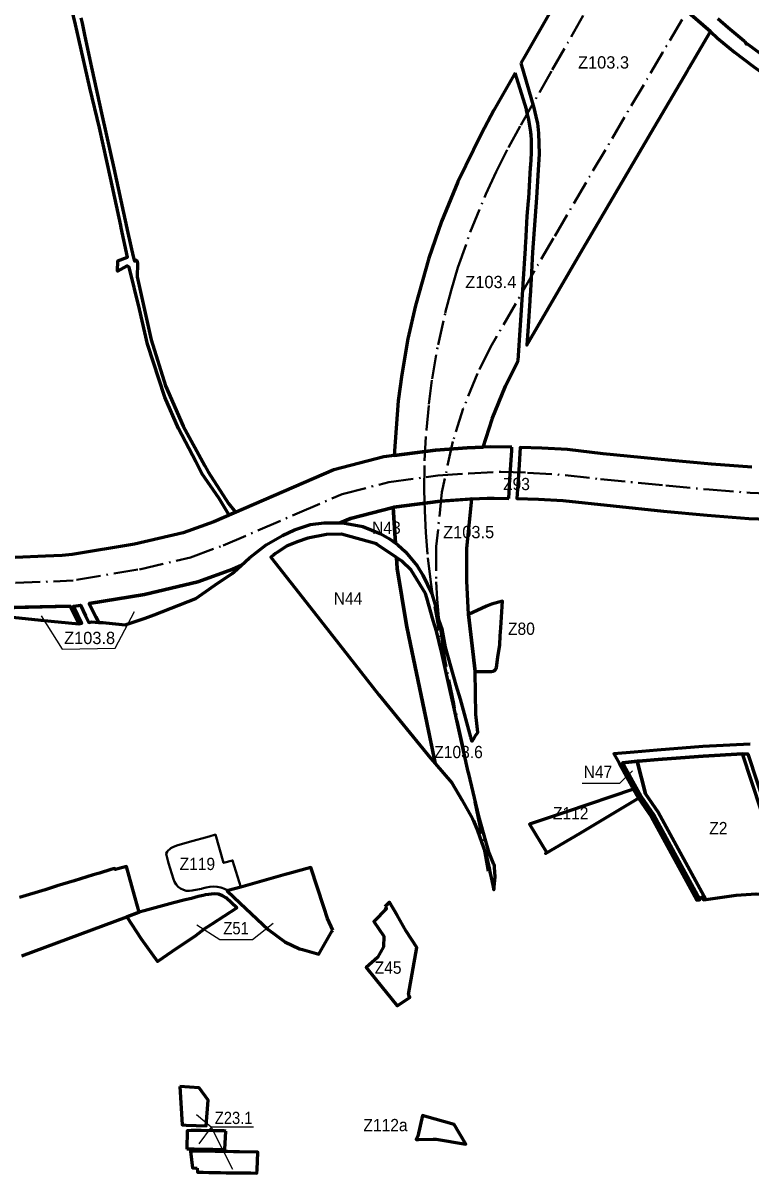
# Model space of a CAD drawing. Extents: x -650277 to -643425, y -1073980 to -1066720.
# Drawn here: x -648765 to -647342, y -1070372 to -1068122 of the extents above; entities that cross this region are included whole.
import ezdxf

# ---------------------------------------------------------------- set-up
doc = ezdxf.new("R2010")
doc.units = 0
doc.header["$LTSCALE"] = 9.6
doc.linetypes.add('DOT_DASHED', pattern=[7.7, 5, -1.2, 0.3, -1.2])
for name, color, linetype, lineweight in [('1', 7, 'Continuous', 60), ('15', 7, 'Continuous', 60), ('3', 7, 'Continuous', 60), ('35', 7, 'Continuous', 60), ('36', 7, 'Continuous', 60), ('42', 7, 'Continuous', 60), ('60', 7, 'Continuous', 60), ('61', 7, 'Continuous', 60), ('62', 7, 'DOT_DASHED', 40), ('63', 7, 'Continuous', 25), ('9', 7, 'Continuous', 60)]:
    doc.layers.add(name, color=color, linetype=linetype, lineweight=lineweight)

msp = doc.modelspace()

# ---------------------------------------------------------------- linework, layer by layer
at = {"layer": '1'}
for points in [[(-647356.899, -1069552.034), (-647433.779, -1069556.106), (-647433.779, -1069556.106), (-647513.66, -1069562.249), (-647514.067, -1069562.282), (-647560.836, -1069566.036), (-647563.104, -1069566.28)], [(-647563.104, -1069566.28), (-647546.777, -1069629.901), (-647521.943, -1069665.763)], [(-647369.3, -1069828.22), (-647330.46, -1069825.51), (-647294.38, -1069826.88), (-647270.09, -1069827.02), (-647266.581, -1069827.042), (-647356.899, -1069552.034)], [(-647521.943, -1069665.763), (-647428.993, -1069836.714), (-647369.3, -1069828.22)], [(-648368.25, -1070289.71), (-648372.1, -1070289.59), (-648380.97, -1070289.44), (-648392.94, -1070289.25), (-648416.93, -1070288.85), (-648420.39, -1070288.79), (-648428.98, -1070288.92), (-648435.93, -1070288.95), (-648444.15, -1070289.16), (-648444.85, -1070324.47)], [(-648444.85, -1070324.47), (-648444.85, -1070324.47), (-648430.02, -1070324.76), (-648418.1, -1070325), (-648406.09, -1070325.23), (-648394.08, -1070325.47), (-648382.06, -1070325.7), (-648370.07, -1070325.94), (-648368.25, -1070289.71)], [(-648307.13, -1070365.57), (-648305.47, -1070331.23), (-648341.46, -1070330.48), (-648353.32, -1070330.23), (-648365.35, -1070329.98), (-648389.43, -1070329.58), (-648401.41, -1070329.39), (-648413.45, -1070329.19), (-648425.43, -1070329), (-648437.65, -1070328.8), (-648433.46, -1070361.94), (-648424.31, -1070362.21)], [(-648424.31, -1070362.21), (-648424.05, -1070370), (-648412.75, -1070370.28), (-648401.35, -1070370.5), (-648390.06, -1070370.72), (-648378.73, -1070370.94), (-648367.67, -1070371.16), (-648355.67, -1070371.28), (-648343.67, -1070371.41), (-648331.67, -1070371.53), (-648319.67, -1070371.65), (-648307.67, -1070371.78), (-648307.13, -1070365.57)]]:
    msp.add_lwpolyline(points, dxfattribs=at)
at = {"layer": '1', "lineweight": 40}
msp.add_lwpolyline([(-648339.05, -1069812.45), (-648363.68, -1069819.31), (-648371.21, -1069815.56), (-648378.1, -1069813.29), (-648385.21, -1069811.91), (-648392.45, -1069811.44), (-648399.68, -1069811.88), (-648406.84, -1069813.23), (-648414.657, -1069815.246), (-648415.99, -1069815.59), (-648430.881, -1069818.663), (-648433.97, -1069819.3), (-648439.89, -1069819.97), (-648445.8, -1069819.51), (-648451.53, -1069817.98), (-648456.88, -1069815.39), (-648461.64, -1069811.86), (-648465.67, -1069807.49), (-648468.82, -1069802.44), (-648470.97, -1069796.9), (-648480.267, -1069765.316), (-648485.44, -1069747.39), (-648485.14, -1069746.55), (-648483.274, -1069743.777), (-648481.79, -1069741.57), (-648477.39, -1069737.44), (-648476.022, -1069736.525), (-648472.4, -1069734.1), (-648464.45, -1069730.89), (-648439.8, -1069724.19), (-648401.288, -1069713.154), (-648388.631, -1069709.738), (-648372.639, -1069765.241), (-648355.015, -1069760.287)], close=True, dxfattribs=at)
at = {"layer": '1'}
msp.add_lwpolyline([(-648458.28, -1070202.26), (-648454.038, -1070277.767), (-648446.18, -1070278.15), (-648406.8, -1070279.32), (-648403.04, -1070229.15), (-648420.7, -1070204.96)], close=True, dxfattribs=at)
at = {"layer": '15'}
for points in [[(-648349.419, -1069079.223), (-648362.06, -1069084.664), (-648381.44, -1069052.48), (-648415.29, -1069003.16), (-648419.78, -1068994.25), (-648427.21, -1068980.13), (-648461.22, -1068915.44), (-648488.09, -1068854.16), (-648521.92, -1068750.34), (-648537.29, -1068681.95), (-648557.4, -1068599.9), (-648559.44, -1068598.37), (-648561.49, -1068596.84), (-648580.66, -1068607.64), (-648579.97, -1068587.39), (-648560.79, -1068580.12), (-648572.95, -1068522.97), (-648573.96, -1068518.34), (-648594.38, -1068425.02), (-648615.87, -1068327.3), (-648634.84, -1068248.76), (-648655.88, -1068153.63), (-648662.71, -1068124.76), (-648677.61, -1068061.74)], [(-648651.89, -1068111.95), (-648649.74, -1068121.95), (-648644.73, -1068145.27), (-648630.99, -1068209.19), (-648610.14, -1068304.32), (-648587.39, -1068405.82), (-648559.91, -1068532.62), (-648549.84, -1068578.65), (-648547.25, -1068588.14), (-648542.93, -1068586.13), (-648541.74, -1068589.27)], [(-648541.74, -1068589.27), (-648541.25, -1068592.3), (-648541.89, -1068618.64), (-648514.35, -1068741.53), (-648486.25, -1068831.83), (-648451.76, -1068910.91), (-648409.15, -1068988.44), (-648402.76, -1069000.2), (-648363.11, -1069061.72), (-648349.419, -1069079.223)], [(-647341.697, -1069532.602), (-647434.969, -1069537.141), (-647523.931, -1069544.499), (-647568.792, -1069548.21), (-647608.81, -1069551.868), (-647598.735, -1069570.026), (-647573.15, -1069616.16), (-647570.37, -1069621.18), (-647560.36, -1069638.39), (-647535.588, -1069674.163), (-647446.322, -1069838.338), (-647441.19, -1069837.6), (-647440.46, -1069836.558), (-647530.471, -1069671.013), (-647555.266, -1069635.207), (-647592.199, -1069569.411), (-647560.836, -1069566.036), (-647514.067, -1069562.282), (-647513.66, -1069562.249), (-647433.779, -1069556.106), (-647433.779, -1069556.106), (-647356.899, -1069552.034), (-647346.554, -1069551.486), (-647256.034, -1069827.107)]]:
    msp.add_lwpolyline(points, dxfattribs=at)
at = {"layer": '3'}
msp.add_lwpolyline([(-648767.83, -1069946.87), (-648562.242, -1069870.301), (-648537.86, -1069861.22), (-648541.06, -1069849.78), (-648546.97, -1069828.68), (-648562.87, -1069771.85), (-648579.63, -1069776.66), (-648584.65, -1069778.1), (-648586.09, -1069775.75), (-648593.59, -1069778.06), (-648615.88, -1069784.93), (-648627.99, -1069788.67), (-648665.05, -1069799.99), (-648698.31, -1069810.16), (-648722.24, -1069817.54), (-648772.48, -1069832.83)], dxfattribs=at)
for points in [[(-648159.1, -1069896.39), (-648169.15, -1069873.81), (-648176.78, -1069851.74), (-648201.83, -1069773.86), (-648247.27, -1069786.64), (-648251.94, -1069787.95), (-648339.05, -1069812.45), (-648363.68, -1069819.31), (-648365.81, -1069819.9), (-648340.38, -1069843.78), (-648285.62, -1069895.71), (-648253.13, -1069919.7), (-648223.99, -1069932.96), (-648218.245, -1069934.595), (-648186.268, -1069943.697), (-648160.04, -1069897.73)], [(-648470.79, -1069843.51), (-648528.11, -1069858.73), (-648537.86, -1069861.22), (-648562.242, -1069870.301), (-648533.79, -1069913.49), (-648502.048, -1069957.969), (-648472.6, -1069937.81), (-648426.82, -1069906.88), (-648409.44, -1069893.25), (-648396.87, -1069885.43), (-648395.03, -1069884.22), (-648347.06, -1069853), (-648367.64, -1069833.35), (-648374.89, -1069829.22), (-648382.8, -1069826.55), (-648391.08, -1069825.45), (-648408.45, -1069827.83), (-648412.74, -1069828.72), (-648422.75, -1069830.78), (-648435.53, -1069834.44), (-648447.98, -1069837.44)], [(-648057.11, -1069851.12), (-648053.61, -1069854.64), (-648078.54, -1069880.01), (-648059.32, -1069908.27), (-648059.5, -1069929.52), (-648071.58, -1069950.39), (-648093.67, -1069969.42), (-648074.96, -1069993.46), (-648032.85, -1070044.73), (-648008.18, -1070028.25), (-648010.44, -1070023.66), (-648010.94, -1070022.65), (-647994.71, -1069930.53), (-648015.11, -1069898.98), (-648032.94, -1069867.46), (-648048.08, -1069841.95)]]:
    msp.add_lwpolyline(points, close=True, dxfattribs=at)
at = {"layer": '35'}
msp.add_lwpolyline([(-647740.74, -1069744.24), (-647742.36, -1069746.93), (-647674.901, -1069706.701), (-647560.36, -1069638.39), (-647570.37, -1069621.18), (-647701.61, -1069665.279), (-647774.11, -1069689.64)], close=True, dxfattribs=at)
at = {"layer": '36'}
msp.add_lwpolyline([(-647962.82, -1070305.9), (-647956.36, -1070305.77), (-647898.82, -1070315.51), (-647921.51, -1070276.76), (-647979.24, -1070260.71), (-647983.6, -1070259.5), (-647992.71, -1070300.01), (-647995.46, -1070306.55), (-647991.12, -1070306.46)], close=True, dxfattribs=at)
at = {"layer": '42'}
for points in [[(-648100.37, -1069107.1), (-648065.16, -1069121.12), (-648048.06, -1069130.81), (-648036.291, -1069139.458), (-648040.705, -1069069.547), (-648124.327, -1069091.181), (-648144.867, -1069099.987), (-648139.27, -1069100.05), (-648100.37, -1069107.1)], [(-647555.266, -1069635.207), (-647530.471, -1069671.013), (-647440.46, -1069836.558), (-647437.46, -1069832.27), (-647433.32, -1069837.33), (-647428.993, -1069836.714), (-647521.943, -1069665.763), (-647546.777, -1069629.901), (-647563.104, -1069566.28), (-647592.199, -1069569.411)]]:
    msp.add_lwpolyline(points, close=True, dxfattribs=at)
at = {"layer": '60'}
for points in [[(-647618.773, -1067899.914), (-647553.628, -1067999.427), (-647472.338, -1068093.096), (-647419.713, -1068138.871)], [(-647295.47, -1068201.09), (-647347.74, -1068162.54), (-647349.59, -1068163.24), (-647350.6, -1068160.26), (-647353.81, -1068157.67), (-647385.13, -1068131.51), (-647405.026, -1068113.904)], [(-647419.713, -1068138.871), (-647405.71, -1068151.74), (-647372.38, -1068179.01), (-647337.74, -1068205.67), (-647334.62, -1068208.02), (-647307.39, -1068227.44), (-647281.64, -1068244.34), (-647234.11, -1068273.04), (-647230.83, -1068274.93), (-647174.56, -1068306.35), (-647142.788, -1068322.462), (-647130.29, -1068328.8), (-647079.16, -1068357.01), (-647032.91, -1068382.51), (-647029.23, -1068384.46), (-646997.06, -1068401.37), (-646929.56, -1068435.42), (-646927.06, -1068436.66)], [(-647864.531, -1068951.823), (-647895.901, -1068953.392), (-647958.168, -1068957.73), (-648038.596, -1068968.281), (-648038.759, -1068968.54)], [(-647808.28, -1068952.066), (-647850.043, -1068951.098), (-647864.531, -1068951.823)], [(-647814.401, -1069052.246), (-647812.34, -1069014.54), (-647808.67, -1068958.06), (-647808.28, -1068952.066)], [(-647338.816, -1068991.19), (-647417.895, -1068984.986), (-647502.412, -1068977.157), (-647629.424, -1068964.608), (-647699.561, -1068956.635), (-647749.978, -1068953.416), (-647792.01, -1068952.442), (-647794.21, -1068986.12), (-647796.13, -1069015.57), (-647798.631, -1069052.508), (-647756.441, -1069053.207), (-647708.401, -1069056.275), (-647511.94, -1069076.703), (-647426.417, -1069084.624), (-647344.902, -1069091.02), (-647270.522, -1069094.255)], [(-648038.759, -1068968.54), (-648038.746, -1068968.301), (-648058.764, -1068970.927), (-648156.739, -1068996.273), (-648392.002, -1069097.554), (-648451.865, -1069119.456), (-648547.243, -1069141.81), (-648668.959, -1069161.838), (-648688.912, -1069163.603), (-648721.315, -1069164.952), (-648781.015, -1069167.44)], [(-648040.705, -1069069.547), (-648039.666, -1069069.279), (-647948.18, -1069057.276), (-647886.615, -1069053.052), (-647856.541, -1069051.548), (-647848.615, -1069051.679), (-647842.888, -1069051.774), (-647814.401, -1069052.246)], [(-648918.889, -1069268.875), (-648673.267, -1069262.895), (-648656.242, -1069297.116), (-648650.06, -1069296.39), (-648650.58, -1069295.34), (-648658.18, -1069280.27), (-648666.827, -1069262.738), (-648665.007, -1069262.694), (-648665.007, -1069262.694), (-648652.716, -1069260.657), (-648642.74, -1069281.93), (-648636.85, -1069294.49), (-648630.82, -1069293.63), (-648617.434, -1069294.508), (-648635.818, -1069257.857), (-648527.693, -1069239.938), (-648423.173, -1069215.44), (-648354.978, -1069190.492), (-648338.523, -1069183.389), (-648322.14, -1069168.56), (-648306.83, -1069156.57), (-648289.25, -1069142.79), (-648257.5, -1069124.41), (-648234.22, -1069113.6), (-648202.46, -1069103.3), (-648175.65, -1069099.64), (-648144.866, -1069099.987), (-648124.327, -1069091.181), (-648040.705, -1069069.547)], [(-648526.15, -1069286.21), (-648508.95, -1069280.01), (-648427.08, -1069247.75), (-648407.73, -1069233.88), (-648389.91, -1069221.86), (-648355.81, -1069198.88), (-648351.77, -1069195.88), (-648338.523, -1069183.389), (-648354.978, -1069190.492)], [(-648354.978, -1069190.492), (-648423.173, -1069215.44), (-648527.693, -1069239.938), (-648635.818, -1069257.857)], [(-648635.818, -1069257.857), (-648622.995, -1069283.455), (-648617.434, -1069294.508)], [(-648617.434, -1069294.508), (-648609.425, -1069295.033), (-648603.228, -1069295.53), (-648565.18, -1069299.46), (-648526.15, -1069286.21)]]:
    msp.add_lwpolyline(points, dxfattribs=at)
for points in [[(-647860.52, -1069390.72), (-647848.24, -1069390.65), (-647845.25, -1069390.07), (-647843.41, -1069389.23), (-647841.81, -1069387.99), (-647840.42, -1069386.51), (-647839.4, -1069384.73), (-647838.79, -1069382.86), (-647836.2, -1069362.68), (-647832.29, -1069338.58), (-647832.29, -1069338.58), (-647831.19, -1069320.69), (-647830.23, -1069305.38), (-647826.928, -1069253.199), (-647848.17, -1069259.21), (-647858.37, -1069263.03), (-647893.553, -1069279.017), (-647880.326, -1069390.832)], [(-648730.66, -1069290.43), (-648656.242, -1069297.116), (-648673.267, -1069262.895), (-648761.189, -1069265.035), (-648918.889, -1069268.875), (-648909.86, -1069270.02), (-648861.49, -1069275.34), (-648785.92, -1069284.2), (-648730.66, -1069290.43)]]:
    msp.add_lwpolyline(points, close=True, dxfattribs=at)
msp.add_arc((-648354.978, -1069190.492), 0.000000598, 264.13978, 298.69712, dxfattribs=at)
at = {"layer": '61'}
msp.add_line((-648038.596, -1068968.281), (-647958.168, -1068957.73), dxfattribs=at)
for points in [[(-647464.94, -1068215.752), (-647461.188, -1068209.373), (-647419.713, -1068138.871), (-647472.338, -1068093.096), (-647553.628, -1067999.427), (-647618.773, -1067899.914), (-647685.819, -1068016.861)], [(-647685.819, -1068016.861), (-647781.346, -1068183.485), (-647791.055, -1068200.507)], [(-647801.797, -1068219.34), (-647843.6, -1068292.629), (-647868.214, -1068337.803), (-647914.339, -1068432.512), (-647946.187, -1068510.254), (-647971.074, -1068581.98), (-647997.27, -1068674.747), (-648011.775, -1068739.718), (-648023.914, -1068809.332), (-648030.73, -1068861.213), (-648038.596, -1068968.281)], [(-647771.413, -1068334.626), (-647774.94, -1068311.47), (-647779.55, -1068292.23), (-647780.07, -1068290.53), (-647801.797, -1068219.34)], [(-647791.055, -1068200.507), (-647765.22, -1068287.94), (-647759.412, -1068313.436)], [(-647768.02, -1068570.36), (-647770.94, -1068622.47), (-647772.85, -1068656.41), (-647773.08, -1068660.57), (-647773.4, -1068665.71), (-647776.5, -1068714.8), (-647778.95, -1068752.433), (-647675.054, -1068572.919), (-647535.844, -1068336.279), (-647464.94, -1068215.752)], [(-647759.412, -1068313.436), (-647758.45, -1068317.66), (-647756.09, -1068337.61), (-647754.99, -1068378.21), (-647757.41, -1068419.98), (-647760.22, -1068463.96), (-647768.02, -1068570.36)], [(-647796.173, -1068782.191), (-647791.77, -1068713.23), (-647786.47, -1068634.37), (-647786.32, -1068632.19), (-647781.85, -1068562.97), (-647781.55, -1068558.38), (-647781.13, -1068551.88), (-647778.24, -1068499.95), (-647775.82, -1068469.74), (-647775.52, -1068464.97), (-647771.74, -1068404.5), (-647771.47, -1068400.07), (-647770.12, -1068377.5), (-647769.92, -1068352.1), (-647770.81, -1068340.29), (-647771.05, -1068337.01), (-647771.413, -1068334.626)], [(-647846.989, -1068896.545), (-647820.883, -1068832.117), (-647797.632, -1068784.713), (-647796.173, -1068782.191)], [(-647958.168, -1068957.73), (-647895.901, -1068953.392), (-647864.531, -1068951.823), (-647847.197, -1068897.199), (-647847.034, -1068896.687), (-647846.989, -1068896.545)], [(-647886.615, -1069053.052), (-647889.927, -1069053.218), (-647948.18, -1069057.276)], [(-647893.553, -1069279.017), (-647896.67, -1069213.573), (-647896.362, -1069149.171), (-647886.615, -1069053.052)], [(-647948.18, -1069057.276), (-648039.666, -1069069.279), (-648040.705, -1069069.548), (-648036.291, -1069139.458)], [(-648036.291, -1069139.458), (-648031.92, -1069142.67), (-648016.36, -1069156.54), (-647993.8, -1069184.11)], [(-648005.47, -1069192.09), (-648024.02, -1069174.7), (-648034.421, -1069167.61)], [(-648034.421, -1069167.61), (-648034.421, -1069167.61), (-648033, -1069189), (-648015, -1069300), (-648010.092, -1069322.087), (-647980.331, -1069465.915), (-647958.34, -1069570.699), (-647925.99, -1069608.57), (-647906.16, -1069641.48), (-647885.665, -1069678.788), (-647885.663, -1069678.794), (-647883.51, -1069682.71), (-647875.82, -1069701.85), (-647875.82, -1069701.85), (-647864.19, -1069735.12), (-647858.44, -1069749.43), (-647852.63, -1069775.7), (-647850.66, -1069785.74), (-647849.165, -1069793.367)], [(-647993.8, -1069184.11), (-647982.58, -1069202.33), (-647965.06, -1069238.95), (-647957.56, -1069264.74), (-647953.01, -1069285.73), (-647951.841, -1069289.09)], [(-647962.2, -1069290.88), (-647974.81, -1069246.86), (-647977.29, -1069238.21), (-648005.47, -1069192.09)], [(-647852.78, -1069745.71), (-647859.722, -1069722.428), (-647872.87, -1069673.56), (-647892.79, -1069591.06), (-647892.789, -1069591.06), (-647893.75, -1069587.08), (-647922.04, -1069459.71), (-647925.16, -1069445.68), (-647928.41, -1069431.03), (-647945.28, -1069355.1), (-647956.27, -1069311.58), (-647962.2, -1069290.88)], [(-647951.841, -1069289.09), (-647945.63, -1069306.95), (-647938.77, -1069343.17), (-647918.08, -1069417.43), (-647909.67, -1069444.46), (-647889.22, -1069519.32), (-647887.087, -1069527.229), (-647885.782, -1069525.389), (-647882.551, -1069520.835), (-647878.73, -1069515.45)], [(-647880.326, -1069390.832), (-647880.326, -1069390.832), (-647893.553, -1069279.017)], [(-647878.73, -1069515.45), (-647874.75, -1069509.84), (-647878.93, -1069475.09), (-647880.318, -1069391.297), (-647880.326, -1069390.832)], [(-647841.402, -1069792.351), (-647842.489, -1069773.282), (-647842.622, -1069770.956), (-647843.337, -1069769.013), (-647843.443, -1069768.293), (-647852.78, -1069745.71)], [(-647849.165, -1069793.367), (-647843.74, -1069817.63), (-647841.402, -1069792.351)]]:
    msp.add_lwpolyline(points, dxfattribs=at)
at = {"layer": '62'}
for points in [[(-647128.118, -1067439.088), (-647164.761, -1067539.408), (-647210.113, -1067645.071), (-647251.182, -1067728.502), (-647325.296, -1067860.04), (-647512.903, -1068178.95), (-647726.877, -1068542.68), (-647850.594, -1068756.441), (-647875.691, -1068807.609), (-647903.473, -1068876.174), (-647924.037, -1068940.973), (-647945.559, -1069039.601), (-647956.348, -1069145.994), (-647956.677, -1069214.977), (-647954.925, -1069248.93), (-647950.785, -1069292.731), (-647945.699, -1069329.377), (-647937.748, -1069374.683)], [(-647855.282, -1069780.988), (-647871.488, -1069692.474), (-647887.497, -1069616.134), (-647904.75, -1069533.925), (-647921.593, -1069453.674), (-647951.177, -1069310.704), (-647961.781, -1069251.651), (-647967.108, -1069216.048), (-647973.483, -1069161.422), (-647976.974, -1069118.566), (-647979.115, -1069076.622), (-647979.994, -1069035.633), (-647979.227, -1068978.642), (-647975.845, -1068917.741), (-647971.102, -1068867.969), (-647964.589, -1068818.397), (-647952.909, -1068751.415), (-647938.965, -1068688.958), (-647927.463, -1068645.455), (-647913.969, -1068600.436), (-647890.042, -1068531.477), (-647859.34, -1068456.533), (-647839.124, -1068413.001), (-647815.115, -1068365.753), (-647791.193, -1068321.849), (-647729.261, -1068213.27), (-647633.767, -1068046.703)], [(-647953.174, -1069007.503), (-647892.914, -1069003.305), (-647829.936, -1069000.155), (-647777.98, -1069001.73), (-647703.981, -1069006.455), (-647634.706, -1069014.33), (-647507.176, -1069026.93), (-647422.156, -1069034.805), (-647341.859, -1069041.105), (-647269.435, -1069044.255), (-647198.585, -1069044.255), (-647126.161, -1069041.105), (-647071.055, -1069037.955), (-646992.775, -1069025.505), (-646951.398, -1069008.03), (-646907.314, -1068982.831), (-646861.655, -1068949.756), (-646819.145, -1068907.232), (-646779.784, -1068863.132), (-646712.083, -1068781.233), (-646669.79, -1068726.705)], [(-648660.841, -1069211.175), (-648537.468, -1069190.874), (-648437.519, -1069167.448), (-648373.49, -1069144.023), (-648228.701, -1069081.527), (-648140.533, -1069043.727), (-648049.215, -1069020.103), (-647953.174, -1069007.503)], [(-649319.032, -1069251.01), (-649228.433, -1069229.954), (-649166.697, -1069221.478), (-649075.909, -1069222.689), (-648779.53, -1069217.422), (-648667.088, -1069212.737)]]:
    msp.add_lwpolyline(points, dxfattribs=at)
at = {"layer": '63'}
for q in [(-648421, -1070315), (-648355.27, -1070364.25)]:
    msp.add_line((-648397, -1070282), q, dxfattribs=at)
for points in [[(-648730, -1069282), (-648689.019, -1069347.095), (-648585, -1069345.095), (-648547, -1069273)], [(-647671, -1069609), (-647597, -1069609), (-647572, -1069585)], [(-648425, -1069886), (-648380, -1069915), (-648316, -1069915), (-648276, -1069883)], [(-648314, -1070282), (-648397, -1070282), (-648426, -1070258)]]:
    msp.add_lwpolyline(points, dxfattribs=at)
at = {"layer": '9'}
msp.add_lwpolyline([(-648015, -1069300), (-648033, -1069189), (-648034.421, -1069167.61), (-648071.9, -1069142.06), (-648073.66, -1069140.86), (-648141.92, -1069121.66), (-648171.14, -1069122.83), (-648207.77, -1069129.95), (-648209.89, -1069130.36), (-648226.51, -1069136.57), (-648248.14, -1069144.65), (-648268.87, -1069158.61), (-648270.92, -1069159.99), (-648275.19, -1069162.87), (-648280.1, -1069166.97), (-648203.01, -1069264.73), (-648127.77, -1069361.38), (-648068.71, -1069436.57), (-647967.53, -1069559.94), (-647958.214, -1069571.3), (-647980.331, -1069465.915), (-648010.092, -1069322.087)], close=True, dxfattribs=at)

# ---------------------------------------------------------------- texts
at = {"layer": '63'}
for s, p in [('Z103.3', (-647679, -1068211)), ('Z103.4', (-647899.646, -1068640.598)), ('Z103.5', (-647942.96, -1069129.881)), ('Z103.8', (-648685, -1069337))]:
    msp.add_text(s, height=24, dxfattribs=at).set_placement(p)
for s, width, p in [('Z93', 0.95, (-647825.651, -1069035.867)), ('N43', 0.95, (-648081.963, -1069121.387)), ('N44', 0.95, (-648157.12, -1069259.712)), ('Z80', 0.95, (-647816, -1069319)), ('Z103.6', 0.95, (-647960.304, -1069560.198)), ('N47', 0.95, (-647668, -1069599)), ('Z112', 0.95, (-647728, -1069680)), ('Z2', 0.95, (-647422, -1069709)), ('Z119', 0.95, (-648458.914, -1069779.092)), ('Z51', 0.9, (-648373.214, -1069904.865)), ('Z45', 0.95, (-648077, -1069982)), ('Z23.1', 0.9, (-648390, -1070276)), ('Z112a', 0.95, (-648099, -1070290))]:
    msp.add_text(s, height=24, dxfattribs=dict(at, width=width)).set_placement(p)

doc.saveas('drawing.dxf')
